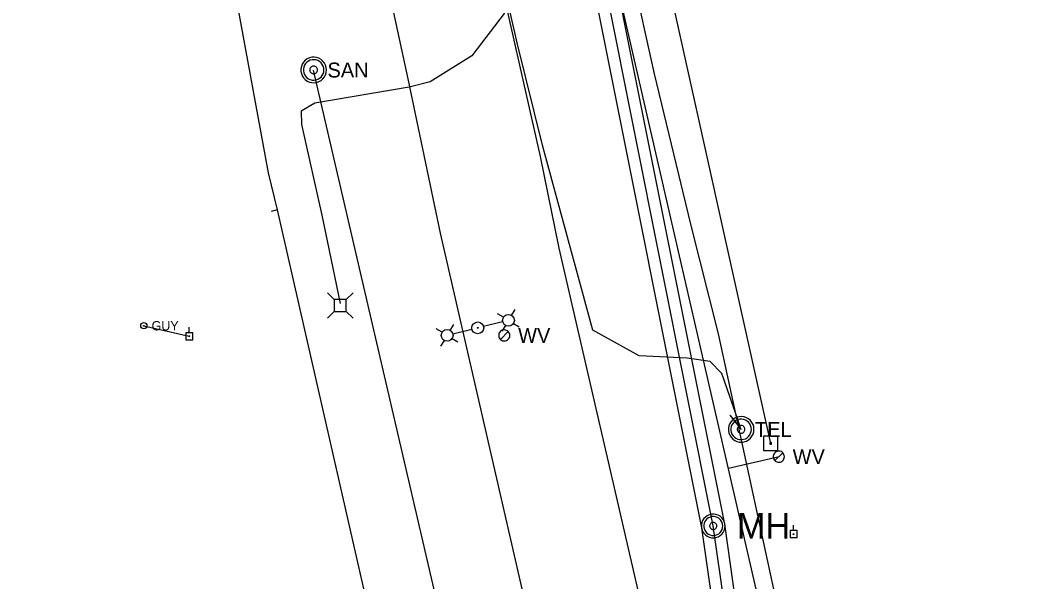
# Model space of a CAD drawing. Extents: x 600849 to 606371, y 330010 to 403088.
# Drawn here: x 604676.1 to 604937, y 339132.8 to 339277.5 of the extents above; entities that cross this region are included whole.
import ezdxf

# ---------------------------------------------------------------- set-up
doc = ezdxf.new("R2010")
doc.units = 0
for name, color, linetype in [('E_LTG', 7, 'Continuous'), ('E_UTL_AG_Bold', 7, 'Continuous'), ('E_UTL_E_UG', 7, 'Continuous'), ('E_UTL_EGuyWire', 7, 'Continuous'), ('E_UTL_EPowerPole', 7, 'Continuous'), ('E_UTL_FO_UG', 7, 'Continuous'), ('E_UTL_G_UG', 7, 'Continuous'), ('E_UTL_Overhead', 7, 'Continuous'), ('E_UTL_SAN', 7, 'Continuous'), ('E_UTL_SAN_UG', 7, 'Continuous'), ('E_UTL_SAN_UG_MMSD', 7, 'Continuous'), ('E_UTL_SAN_UG_OUTER_LIMITS', 7, 'Continuous'), ('E_UTL_T_MH', 7, 'Continuous'), ('E_UTL_T_UG', 7, 'Continuous'), ('E_UTL_W', 7, 'Continuous'), ('E_UTL_W_UG', 7, 'Continuous')]:
    doc.layers.add(name, color=color, linetype=linetype)

# ---------------------------------------------------------------- blocks, each defined once
blk = doc.blocks.new('ACAD_PROXY_ENTITY_1')
at = {"layer": 'E_UTL_SAN'}
for points in [[(1844102.38, 1030298.31), (1844102.21, 1030300.07), (1844101.71, 1030301.77), (1844100.9, 1030303.34), (1844099.81, 1030304.74), (1844098.47, 1030305.9), (1844096.93, 1030306.78), (1844095.26, 1030307.36), (1844093.51, 1030307.61), (1844091.74, 1030307.53), (1844090.02, 1030307.11), (1844088.41, 1030306.38), (1844086.97, 1030305.35), (1844085.74, 1030304.07), (1844084.79, 1030302.58), (1844084.13, 1030300.93), (1844083.79, 1030299.19), (1844083.79, 1030297.42), (1844084.13, 1030295.69), (1844084.79, 1030294.04), (1844085.74, 1030292.55), (1844086.97, 1030291.27), (1844088.41, 1030290.24), (1844090.02, 1030289.51), (1844091.74, 1030289.09), (1844093.51, 1030289.01), (1844095.26, 1030289.26), (1844096.93, 1030289.84), (1844098.47, 1030290.72), (1844099.81, 1030291.88), (1844100.9, 1030293.27), (1844101.71, 1030294.85), (1844102.21, 1030296.55), (1844102.38, 1030298.31)], [(1844100.52, 1030298.31), (1844100.38, 1030299.72), (1844099.98, 1030301.08), (1844099.33, 1030302.34), (1844098.46, 1030303.45), (1844097.39, 1030304.38), (1844096.16, 1030305.09), (1844094.82, 1030305.55), (1844093.42, 1030305.75), (1844092.01, 1030305.68), (1844090.63, 1030305.35), (1844089.34, 1030304.76), (1844088.19, 1030303.94), (1844087.21, 1030302.92), (1844086.44, 1030301.72), (1844085.92, 1030300.41), (1844085.65, 1030299.02), (1844085.65, 1030297.6), (1844085.92, 1030296.21), (1844086.44, 1030294.9), (1844087.21, 1030293.7), (1844088.19, 1030292.68), (1844089.34, 1030291.86), (1844090.63, 1030291.27), (1844092.01, 1030290.93), (1844093.42, 1030290.87), (1844094.82, 1030291.07), (1844096.16, 1030291.53), (1844097.39, 1030292.24), (1844098.46, 1030293.17), (1844099.33, 1030294.28), (1844099.98, 1030295.54), (1844100.38, 1030296.9), (1844100.52, 1030298.31)], [(1844095.86, 1030298.31), (1844095.81, 1030298.84), (1844095.66, 1030299.35), (1844095.42, 1030299.82), (1844095.09, 1030300.24), (1844094.69, 1030300.59), (1844094.23, 1030300.85), (1844093.72, 1030301.02), (1844093.2, 1030301.1), (1844092.67, 1030301.08), (1844092.15, 1030300.95), (1844091.67, 1030300.73), (1844091.24, 1030300.42), (1844090.87, 1030300.04), (1844090.58, 1030299.59), (1844090.38, 1030299.1), (1844090.28, 1030298.58), (1844090.28, 1030298.04), (1844090.38, 1030297.52), (1844090.58, 1030297.03), (1844090.87, 1030296.58), (1844091.24, 1030296.2), (1844091.67, 1030295.89), (1844092.15, 1030295.67), (1844092.67, 1030295.54), (1844093.2, 1030295.52), (1844093.72, 1030295.59), (1844094.23, 1030295.77), (1844094.69, 1030296.03), (1844095.09, 1030296.38), (1844095.42, 1030296.8), (1844095.66, 1030297.27), (1844095.81, 1030297.78), (1844095.86, 1030298.31)]]:
    blk.add_lwpolyline(points, dxfattribs=at)
blk.add_text('MH', height=20.117, dxfattribs=at).set_placement((1844111.69, 1030288.25))
blk = doc.blocks.new('PPOL')
at = {"layer": 'E_UTL_EPowerPole'}
blk.add_line((-0.2, 13.7), (-0.2, 35.3), dxfattribs=at)
blk.add_lwpolyline([(-13.9, -13.7), (13.5, -13.7), (13.5, 13.7), (-13.9, 13.7)], close=True, dxfattribs=at)
blk.add_circle((0, 0), 1.77, dxfattribs=at)
blk = doc.blocks.new('GUY')
at = {"layer": 'E_UTL_EGuyWire'}
for radius in [12.2, 1.52]:
    blk.add_circle((0, 0), radius, dxfattribs=at)
blk.add_text('GUY', height=36.58, dxfattribs=at).set_placement((30.5, -18.3))

msp = doc.modelspace()

# ---------------------------------------------------------------- linework, layer by layer
at = {"layer": 'E_LTG'}
for p, q in [((604800.51, 339200.96), (604799.01, 339201.87)), ((604802.58, 339201.47), (604803.5, 339202.97)), ((604786.79, 339197.61), (604787.71, 339199.12)), ((604800.29, 339199.81), (604795.41, 339198.62)), ((604801.02, 339198.89), (604800.1, 339197.38)), ((604803.09, 339199.39), (604804.59, 339198.48)), ((604784.72, 339197.11), (604783.22, 339198.02)), ((604787.51, 339196.69), (604792.4, 339197.88)), ((604785.23, 339195.03), (604784.31, 339193.53)), ((604787.3, 339195.54), (604788.8, 339194.63))]:
    msp.add_line(p, q, dxfattribs=at)
for centre, radius in [((604801.8, 339200.18), 1.52), ((604793.9, 339198.25), 1.52), ((604786.01, 339196.32), 1.52), ((604793.9, 339198.25), 0.117)]:
    msp.add_circle(centre, radius, dxfattribs=at)
at = {"layer": 'E_UTL_AG_Bold'}
for points in [[(604756.95, 339205.56), (604755.2, 339207.31)], [(604760.05, 339205.56), (604761.8, 339207.31)], [(604760.05, 339205.56), (604756.95, 339205.56)], [(604756.95, 339205.56), (604756.95, 339202.46)], [(604760.05, 339202.46), (604760.05, 339205.56)], [(604756.95, 339202.46), (604755.2, 339200.71)], [(604756.95, 339202.46), (604760.05, 339202.46)], [(604760.05, 339202.46), (604761.8, 339200.71)]]:
    msp.add_lwpolyline(points, dxfattribs=at)
at = {"layer": 'E_UTL_E_UG'}
msp.add_line((604875.51, 338824.32), (604784.34, 339222.62), dxfattribs=at)
msp.add_lwpolyline([(604784.34, 339222.62), (604775.95, 339262.38), (604768.41, 339297.38), (604762.12, 339328.3), (604757.39, 339350.58), (604755.47, 339358.12), (604755.17, 339359.69), (604751.45, 339378.59), (604743.59, 339418.09), (604735.46, 339449.75), (604728.77, 339482.52), (604722.85, 339509.42)], dxfattribs=at)
at = {"layer": 'E_UTL_EGuyWire'}
msp.add_line((604707.93, 339198.79), (604719.64, 339196.1), dxfattribs=at)
at = {"layer": 'E_UTL_EPowerPole'}
for points in [[(604869.28, 339170.33), (604869.28, 339173.24)], [(604871.12, 339170.33), (604867.43, 339170.33)], [(604867.43, 339170.33), (604867.43, 339166.64)], [(604871.12, 339166.64), (604871.12, 339170.33)], [(604869.55, 339168.49), (604869.54, 339168.54), (604869.53, 339168.58), (604869.51, 339168.62), (604869.48, 339168.66), (604869.45, 339168.69), (604869.41, 339168.71), (604869.37, 339168.72), (604869.32, 339168.73), (604869.28, 339168.73), (604869.23, 339168.72), (604869.19, 339168.7), (604869.15, 339168.67), (604869.12, 339168.64), (604869.1, 339168.6), (604869.08, 339168.56), (604869.07, 339168.51), (604869.07, 339168.47), (604869.08, 339168.42), (604869.1, 339168.38), (604869.12, 339168.34), (604869.15, 339168.31), (604869.19, 339168.28), (604869.23, 339168.27), (604869.28, 339168.26), (604869.32, 339168.25), (604869.37, 339168.26), (604869.41, 339168.27), (604869.45, 339168.3), (604869.48, 339168.33), (604869.51, 339168.36), (604869.53, 339168.4), (604869.54, 339168.45), (604869.55, 339168.49)], [(604867.43, 339166.64), (604871.12, 339166.64)]]:
    msp.add_lwpolyline(points, dxfattribs=at)
at = {"layer": 'E_UTL_FO_UG'}
msp.add_lwpolyline([(604858.79, 339175.74), (604861.69, 339172.1)], dxfattribs=at)
at = {"layer": 'E_UTL_G_UG'}
for p, q in [((604843.56, 338783.61), (604742.35, 339228.68)), ((604914.69, 338786.08), (604814.85, 339218.78))]:
    msp.add_line(p, q, dxfattribs=at)
for points in [[(604814.85, 339218.78), (604810.09, 339242.37), (604799.43, 339289.54), (604793.26, 339314.06), (604787.02, 339344.67), (604774.66, 339399.62), (604767.29, 339432.61), (604758.85, 339472.19), (604751.42, 339503.86)], [(604742.35, 339228.68), (604740.05, 339238.17), (604732.17, 339281.15), (604723.13, 339319.31), (604718.15, 339342.27), (604709.95, 339377.23), (604705.89, 339396.14), (604699.95, 339418.23), (604694.75, 339444.39), (604689.12, 339468.85), (604685.03, 339486.7), (604684.68, 339487.29), (604678.37, 339490.44), (604676.2, 339500.02)], [(604848.74, 339224.99), (604839.38, 339263.68), (604833.64, 339289.73), (604829.38, 339309.27), (604842.98, 339310.1), (604884.47, 339308.8), (604885.27, 339308.62), (604944.46, 339308.43), (604976.87, 339308.43), (605026.37, 339307.52), (605035.2, 339307.44)], [(604742.35, 339228.68), (604740.7, 339228.23)], [(604930.39, 338852.74), (604855.87, 339196.73), (604848.74, 339224.99)]]:
    msp.add_lwpolyline(points, dxfattribs=at)
at = {"layer": 'E_UTL_Overhead'}
msp.add_lwpolyline([(604869.31, 339168.49), (604840.42, 339298.76)], dxfattribs=at)
at = {"layer": 'E_UTL_SAN'}
for points in [[(604754.94, 339264.68), (604754.88, 339265.31), (604754.71, 339265.91), (604754.42, 339266.47), (604754.03, 339266.96), (604753.56, 339267.37), (604753.01, 339267.68), (604752.42, 339267.89), (604751.8, 339267.98), (604751.17, 339267.95), (604750.56, 339267.8), (604749.99, 339267.54), (604749.48, 339267.18), (604749.05, 339266.72), (604748.71, 339266.19), (604748.48, 339265.61), (604748.36, 339265), (604748.36, 339264.37), (604748.48, 339263.75), (604748.71, 339263.17), (604749.05, 339262.64), (604749.48, 339262.19), (604749.99, 339261.82), (604750.56, 339261.56), (604751.17, 339261.42), (604751.8, 339261.39), (604752.42, 339261.48), (604753.01, 339261.68), (604753.56, 339261.99), (604754.03, 339262.41), (604754.42, 339262.9), (604754.71, 339263.46), (604754.88, 339264.06), (604754.94, 339264.68)], [(604754.28, 339264.68), (604754.23, 339265.18), (604754.09, 339265.66), (604753.86, 339266.11), (604753.55, 339266.5), (604753.17, 339266.83), (604752.74, 339267.08), (604752.26, 339267.25), (604751.77, 339267.32), (604751.27, 339267.3), (604750.78, 339267.18), (604750.32, 339266.97), (604749.91, 339266.68), (604749.57, 339266.31), (604749.3, 339265.89), (604749.11, 339265.43), (604749.01, 339264.93), (604749.01, 339264.43), (604749.11, 339263.94), (604749.3, 339263.47), (604749.57, 339263.05), (604749.91, 339262.69), (604750.32, 339262.4), (604750.78, 339262.19), (604751.27, 339262.07), (604751.77, 339262.05), (604752.26, 339262.12), (604752.74, 339262.28), (604753.17, 339262.53), (604753.55, 339262.86), (604753.86, 339263.26), (604754.09, 339263.7), (604754.23, 339264.18), (604754.28, 339264.68)], [(604752.63, 339264.68), (604752.61, 339264.87), (604752.56, 339265.05), (604752.48, 339265.22), (604752.36, 339265.37), (604752.22, 339265.49), (604752.05, 339265.58), (604751.88, 339265.64), (604751.69, 339265.67), (604751.5, 339265.66), (604751.32, 339265.62), (604751.15, 339265.54), (604750.99, 339265.43), (604750.86, 339265.29), (604750.76, 339265.14), (604750.69, 339264.96), (604750.66, 339264.78), (604750.66, 339264.59), (604750.69, 339264.4), (604750.76, 339264.23), (604750.86, 339264.07), (604750.99, 339263.93), (604751.15, 339263.83), (604751.32, 339263.75), (604751.5, 339263.7), (604751.69, 339263.69), (604751.88, 339263.72), (604752.05, 339263.78), (604752.22, 339263.88), (604752.36, 339264), (604752.48, 339264.15), (604752.56, 339264.31), (604752.61, 339264.5), (604752.63, 339264.68)]]:
    msp.add_lwpolyline(points, dxfattribs=at)
at = {"layer": 'E_UTL_SAN_UG'}
msp.add_lwpolyline([(604802.36, 339046.2), (604751.63, 339264.67)], dxfattribs=at)
at = {"layer": 'E_UTL_SAN_UG_MMSD'}
for p, q in [((604854.51, 339147.21), (604642.2, 340212.1)), ((605016.2, 338023.67), (604854.51, 339147.21))]:
    msp.add_line(p, q, dxfattribs=at)
at = {"layer": 'E_UTL_SAN_UG_OUTER_LIMITS'}
for p, q in [((604851.55, 339146.7), (604639.25, 340211.51)), ((604857.47, 339147.72), (604645.14, 340212.68)), ((605012.73, 338026.74), (604851.55, 339146.7)), ((605019.67, 338020.62), (604857.47, 339147.72))]:
    msp.add_line(p, q, dxfattribs=at)
at = {"layer": 'E_UTL_T_MH'}
for points in [[(604864.99, 339172.1), (604864.93, 339172.73), (604864.76, 339173.33), (604864.47, 339173.89), (604864.08, 339174.38), (604863.61, 339174.79), (604863.06, 339175.1), (604862.47, 339175.31), (604861.85, 339175.4), (604861.22, 339175.37), (604860.61, 339175.22), (604860.04, 339174.96), (604859.53, 339174.6), (604859.1, 339174.14), (604858.76, 339173.61), (604858.53, 339173.03), (604858.41, 339172.42), (604858.41, 339171.79), (604858.53, 339171.17), (604858.76, 339170.59), (604859.1, 339170.06), (604859.53, 339169.61), (604860.04, 339169.24), (604860.61, 339168.98), (604861.22, 339168.84), (604861.85, 339168.81), (604862.47, 339168.9), (604863.06, 339169.1), (604863.61, 339169.41), (604864.08, 339169.83), (604864.47, 339170.32), (604864.76, 339170.88), (604864.93, 339171.48), (604864.99, 339172.1)], [(604864.33, 339172.1), (604864.28, 339172.6), (604864.14, 339173.08), (604863.91, 339173.53), (604863.6, 339173.92), (604863.22, 339174.25), (604862.79, 339174.5), (604862.31, 339174.67), (604861.82, 339174.74), (604861.32, 339174.72), (604860.83, 339174.6), (604860.37, 339174.39), (604859.96, 339174.1), (604859.62, 339173.73), (604859.35, 339173.31), (604859.16, 339172.85), (604859.06, 339172.35), (604859.06, 339171.85), (604859.16, 339171.36), (604859.35, 339170.89), (604859.62, 339170.47), (604859.96, 339170.11), (604860.37, 339169.82), (604860.83, 339169.61), (604861.32, 339169.49), (604861.82, 339169.47), (604862.31, 339169.54), (604862.79, 339169.7), (604863.22, 339169.95), (604863.6, 339170.28), (604863.91, 339170.68), (604864.14, 339171.12), (604864.28, 339171.6), (604864.33, 339172.1)], [(604862.68, 339172.1), (604862.66, 339172.29), (604862.61, 339172.47), (604862.52, 339172.64), (604862.41, 339172.79), (604862.27, 339172.91), (604862.1, 339173), (604861.93, 339173.06), (604861.74, 339173.09), (604861.55, 339173.08), (604861.37, 339173.04), (604861.2, 339172.96), (604861.04, 339172.85), (604860.91, 339172.71), (604860.81, 339172.56), (604860.74, 339172.38), (604860.71, 339172.2), (604860.71, 339172.01), (604860.74, 339171.82), (604860.81, 339171.65), (604860.91, 339171.49), (604861.04, 339171.35), (604861.2, 339171.25), (604861.37, 339171.17), (604861.55, 339171.12), (604861.74, 339171.11), (604861.93, 339171.14), (604862.1, 339171.2), (604862.27, 339171.3), (604862.41, 339171.42), (604862.52, 339171.57), (604862.61, 339171.73), (604862.66, 339171.92), (604862.68, 339172.1)]]:
    msp.add_lwpolyline(points, dxfattribs=at)
at = {"layer": 'E_UTL_T_UG'}
for points in [[(604801.08, 339284.89), (604800.73, 339279.22), (604792.4, 339268.31), (604781.64, 339261.64), (604776.22, 339260.28), (604751.92, 339256.11), (604748.44, 339254.09), (604748.54, 339250.65), (604753.73, 339227.31), (604758.47, 339204.5)], [(604861.66, 339172.14), (604860.9, 339174.37), (604856.77, 339186.5), (604853.76, 339189.54), (604847.78, 339190.4), (604835.42, 339191.04), (604823.52, 339197.63), (604810.64, 339244.98), (604804.14, 339271.36), (604801.08, 339284.89)]]:
    msp.add_lwpolyline(points, dxfattribs=at)
at = {"layer": 'E_UTL_W'}
for points in [[(604802.15, 339196.29), (604802.12, 339196.56), (604802.04, 339196.82), (604801.92, 339197.06), (604801.75, 339197.28), (604801.55, 339197.45), (604801.31, 339197.59), (604801.06, 339197.68), (604800.79, 339197.72), (604800.52, 339197.7), (604800.25, 339197.64), (604800.01, 339197.53), (604799.79, 339197.37), (604799.6, 339197.17), (604799.45, 339196.95), (604799.35, 339196.69), (604799.3, 339196.43), (604799.3, 339196.16), (604799.35, 339195.89), (604799.45, 339195.64), (604799.6, 339195.41), (604799.79, 339195.21), (604800.01, 339195.06), (604800.25, 339194.94), (604800.52, 339194.88), (604800.79, 339194.87), (604801.06, 339194.91), (604801.31, 339194.99), (604801.55, 339195.13), (604801.75, 339195.31), (604801.92, 339195.52), (604802.04, 339195.76), (604802.12, 339196.02), (604802.15, 339196.29)], [(604799.71, 339195.28), (604801.73, 339197.3)], [(604872.83, 339165.06), (604872.8, 339165.33), (604872.72, 339165.59), (604872.6, 339165.83), (604872.43, 339166.05), (604872.23, 339166.22), (604871.99, 339166.36), (604871.74, 339166.45), (604871.47, 339166.49), (604871.2, 339166.47), (604870.93, 339166.41), (604870.69, 339166.3), (604870.47, 339166.14), (604870.28, 339165.94), (604870.13, 339165.72), (604870.03, 339165.46), (604869.98, 339165.2), (604869.98, 339164.93), (604870.03, 339164.66), (604870.13, 339164.41), (604870.28, 339164.18), (604870.47, 339163.98), (604870.69, 339163.83), (604870.93, 339163.71), (604871.2, 339163.65), (604871.47, 339163.64), (604871.74, 339163.68), (604871.99, 339163.76), (604872.23, 339163.9), (604872.43, 339164.08), (604872.6, 339164.29), (604872.72, 339164.53), (604872.8, 339164.79), (604872.83, 339165.06)], [(604870.39, 339164.05), (604872.41, 339166.07)]]:
    msp.add_lwpolyline(points, dxfattribs=at)
at = {"layer": 'E_UTL_W_UG'}
msp.add_line((604858.41, 339162.1), (604871.52, 339165.12), dxfattribs=at)
msp.add_lwpolyline([(604874.94, 339090.23), (604823.66, 339313.21)], dxfattribs=at)

# ---------------------------------------------------------------- block references
at = {"layer": 'E_UTL_EGuyWire', "xscale": 0.06561666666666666, "yscale": 0.06561666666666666}
msp.add_blockref('GUY', (604707.93, 339198.79), dxfattribs=at)
at = {"layer": 'E_UTL_EPowerPole', "xscale": 0.06561666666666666, "yscale": 0.06561666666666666}
for p in [(604719.64, 339196.1), (604875.22, 339145.11)]:
    msp.add_blockref('PPOL', p, dxfattribs=at)
at = {"layer": 'E_UTL_SAN', "xscale": 0.32808333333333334, "yscale": 0.32808333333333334}
msp.add_blockref('ACAD_PROXY_ENTITY_1', (-161.69, 1123.51), dxfattribs=at)

# ---------------------------------------------------------------- texts
at = {"layer": 'E_UTL_SAN'}
msp.add_text('SAN', height=3.849, dxfattribs=at).set_placement((604755.21, 339262.74))
at = {"layer": 'E_UTL_T_MH'}
msp.add_text('TEL', height=3.849, dxfattribs=at).set_placement((604865.26, 339170.16))
at = {"layer": 'E_UTL_W'}
for p in [(604804.29, 339194.37), (604874.97, 339163.14)]:
    msp.add_text('WV', height=3.85, dxfattribs=at).set_placement(p)

doc.saveas('drawing.dxf')
